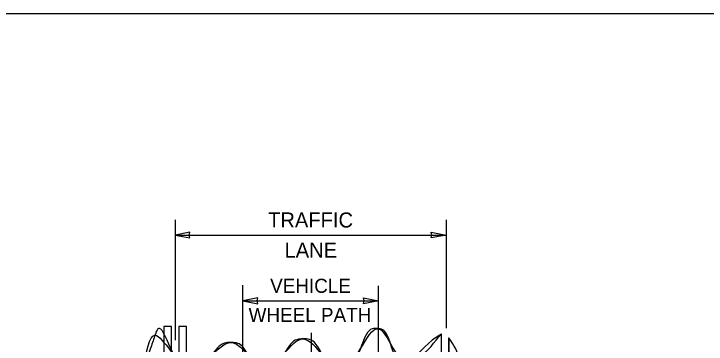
# Model space of a CAD drawing. Extents: x 99862 to 103151, y 100000 to 105076.
# Drawn here: x 100749 to 101485, y 104724 to 105076 of the extents above; entities that cross this region are included whole.
import ezdxf

# ---------------------------------------------------------------- set-up
doc = ezdxf.new("R2010")
doc.units = 0
for name, color, linetype in [('Level 1', 7, 'Continuous'), ('Level 15', 7, 'Continuous'), ('Level 2', 7, 'Continuous'), ('Level 20', 7, 'Continuous'), ('Level 3', 7, 'Continuous'), ('Level 6', 7, 'Continuous')]:
    doc.layers.add(name, color=color, linetype=linetype)

msp = doc.modelspace()

# ---------------------------------------------------------------- linework, layer by layer
at = {"layer": 'Level 1'}
msp.add_lwpolyline([(99862, 102999.5), (103151, 102999.5), (103151, 105075.5), (99862, 105075.5)], close=True, dxfattribs=at)
at = {"layer": 'Level 15'}
for p, q in [((100920.5, 104856.31), (100920.5, 104728.47)), ((101208.5, 104856.31), (101208.5, 104741.09)), ((100920.5, 104840.31), (101208.5, 104840.31)), ((100920.5, 104789.04), (100920.5, 104788.82)), ((100992.5, 104750.73), (100992.5, 104786.95)), ((100992.5, 104698.08), (100992.5, 104786.31)), ((101136.5, 104698.08), (101136.5, 104786.31)), ((101136.5, 104742.85), (101136.5, 104782.75)), ((100992.5, 104770.31), (101136.5, 104770.31)), ((101065.1, 104736.25), (101065.1, 104421.52))]:
    msp.add_line(p, q, dxfattribs=at)
for points in [[(100920.5, 104840.31), (100936.23, 104837.23), (100935.5, 104840.31), (100936.23, 104843.39)], [(101208.5, 104840.31), (101192.78, 104837.23), (101193.5, 104840.31), (101192.78, 104843.39)], [(100992.5, 104770.31), (101008.23, 104767.23), (101007.5, 104770.31), (101008.23, 104773.39)], [(101136.5, 104770.31), (101120.78, 104767.23), (101121.5, 104770.31), (101120.78, 104773.39)]]:
    msp.add_lwpolyline(points, close=True, dxfattribs=at)
at = {"layer": 'Level 2'}
for points in [[(100908.5, 104742.91), (100908.5, 104289.25)], [(100916.5, 104287.58), (100916.5, 104742.91), (100908.5, 104742.91)], [(100916.5, 104742.91), (100908.5, 104742.91), (100908.5, 104287.58)], [(100916.5, 104287.58), (100916.5, 104742.91)], [(100932.5, 104287.58), (100932.5, 104742.91), (100924.5, 104742.91), (100924.5, 104287.58)], [(100932.5, 104742.91), (100924.5, 104742.91), (100924.5, 104287.58)], [(100932.5, 104287.58), (100932.5, 104742.91)]]:
    msp.add_lwpolyline(points, dxfattribs=at)
at = {"layer": 'Level 3'}
for points in [[(101203.5, 104304.19), (101203.5, 104735.06)], [(101211.5, 104730.76), (101211.5, 104312.37)]]:
    msp.add_lwpolyline(points, dxfattribs=at)
for points in [[(101203.5, 104735.06), (101189.2, 104726.8), (101171.68, 104704.04), (101162.48, 104706.21), (101153.39, 104708.36), (101145.87, 104739.61), (101136.5, 104740.72), (101123.34, 104742.27), (101110.76, 104694.9), (101096.12, 104695.37), (101083.48, 104695.77), (101070.27, 104730.12), (101056.56, 104729.82), (101043.03, 104729.53), (101029.28, 104697.2), (101015.73, 104697.92), (101004.11, 104698.53), (100992.89, 104725.36), (100981.27, 104725.99), (100967.89, 104726.72), (100951.62, 104700.24), (100937.25, 104699.83), (100922.92, 104699.43), (100904.44, 104749.77), (100898.97, 104733.65), (100894.93, 104721.74), (100890.89, 104709.83), (100886.85, 104697.92)], [(101227.9, 104312.21), (101226.51, 104328.86), (101218.37, 104375.58), (101219.56, 104392.05), (101220.45, 104404.46), (101227.17, 104416.61), (101227.85, 104429.06), (101229.36, 104456.8), (101219.14, 104485.51), (101220.83, 104513.28), (101222.04, 104533.02), (101234.04, 104552.15), (101233.59, 104571.98), (101232.89, 104602.91), (101225.07, 104634.03), (101223.38, 104665.13), (101222.83, 104675.29), (101223.89, 104685.55), (101223.38, 104695.76), (101222.78, 104707.86), (101219.36, 104719.4), (101211.9, 104730.21), (101211.77, 104730.4), (101211.64, 104730.58), (101211.5, 104730.76)]]:
    msp.add_open_spline(points, degree=3, dxfattribs=at)
msp.add_spline([(100886.85, 104697.92), (100898.97, 104733.65), (100937.25, 104699.83), (100981.27, 104725.99), (101015.73, 104697.92), (101056.56, 104729.82), (101096.12, 104695.37), (101136.5, 104740.72), (101162.48, 104706.21), (101203.5, 104735.41)], degree=3, dxfattribs=at)
at = {"layer": 'Level 6'}
msp.add_line((101211.5, 104312.37), (101211.5, 104730.85), dxfattribs=at)
for points in [[(101203.5, 104304.23), (101203.5, 104735.41)], [(100908.28, 104731.2), (100908.28, 104289.53)]]:
    msp.add_lwpolyline(points, dxfattribs=at)

# ---------------------------------------------------------------- texts
at = {"layer": 'Level 20'}
for s, height, p in [('TRAFFIC', 16, (101019.24, 104848.31)), ('LANE', 16, (101036.73, 104816.31)), ('VEHICLE', 15, (101021.48, 104778.81)), ('WHEEL PATH', 15, (100998.56, 104747.81))]:
    msp.add_text(s, height=height, rotation=360, dxfattribs=at).set_placement(p)

doc.saveas('drawing.dxf')
